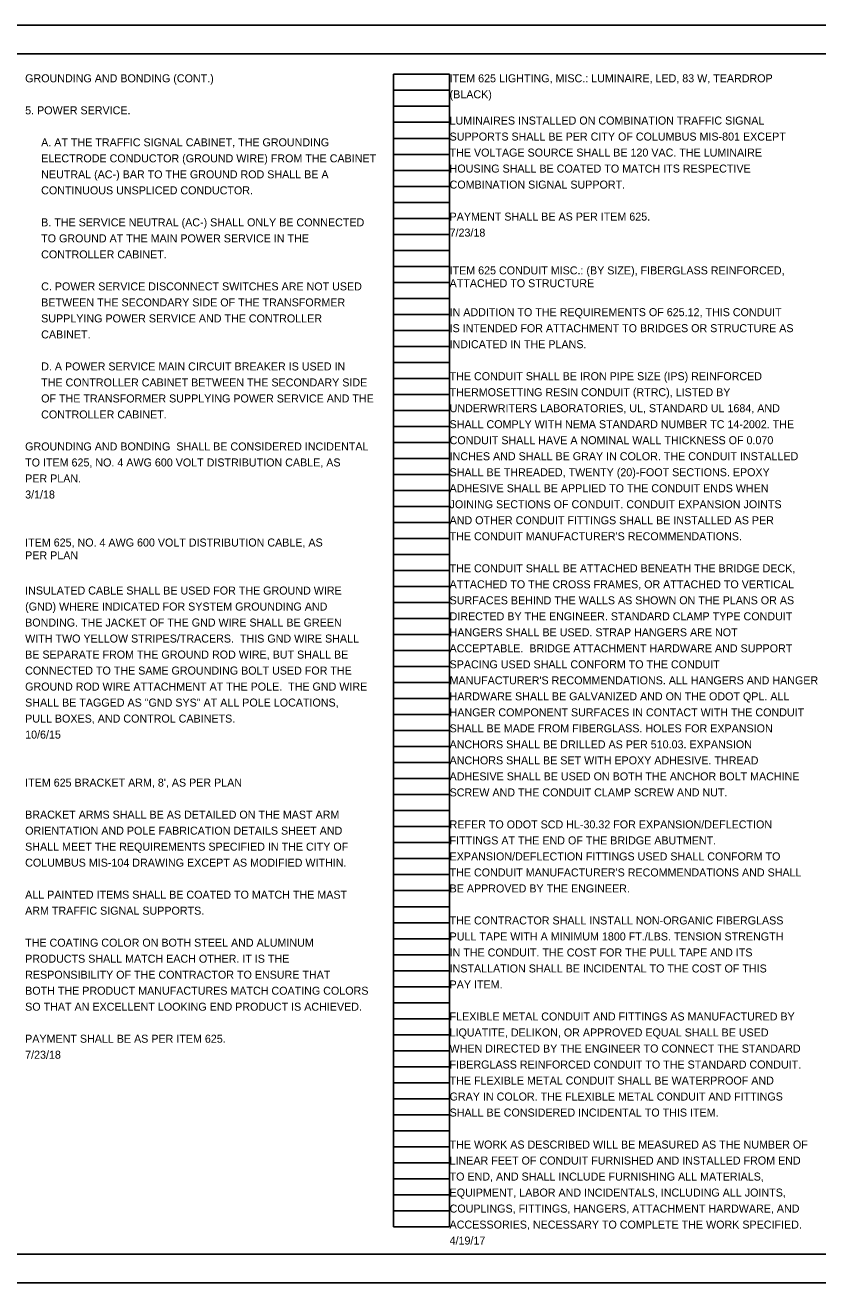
# Model space of a CAD drawing. Extents: x -25.6 to 66.7, y -23.1 to 37.2.
# Drawn here: x 9.81 to 23.67, y -7.51 to 14.49 of the extents above; entities that cross this region are included whole.
import ezdxf

# ---------------------------------------------------------------- set-up
doc = ezdxf.new("R2010")
doc.units = 0
for name, color, linetype in [('PF_P_Text', 7, 'Continuous'), ('SC_Scratch1', 7, 'Continuous'), ('SH_Cut_Line', 7, 'Continuous'), ('SH_Text', 7, 'Continuous')]:
    doc.layers.add(name, color=color, linetype=linetype)

msp = doc.modelspace()

# ---------------------------------------------------------------- linework, layer by layer
at = {"layer": 'PF_P_Text'}
msp.add_lwpolyline([(1.494, 13.992), (32.994, 13.992), (32.994, -7.008), (1.494, -7.008)], close=True, dxfattribs=at)
at = {"layer": 'SC_Scratch1'}
for p, q in [((16.254, -6.528), (16.254, 13.632)), ((16.254, 13.632), (17.234, 13.632)), ((17.234, -6.528), (17.234, 13.632)), ((16.254, 13.352), (17.234, 13.352)), ((16.254, 13.072), (17.234, 13.072)), ((16.254, 12.792), (17.234, 12.792)), ((16.254, 12.512), (17.234, 12.512)), ((16.254, 12.232), (17.234, 12.232)), ((16.254, 11.952), (17.234, 11.952)), ((16.254, 11.672), (17.234, 11.672)), ((16.254, 11.392), (17.234, 11.392)), ((16.254, 11.112), (17.234, 11.112)), ((16.254, 10.832), (17.234, 10.832)), ((16.254, 10.552), (17.234, 10.552)), ((16.254, 10.272), (17.234, 10.272)), ((16.254, 9.992), (17.234, 9.992)), ((16.254, 9.712), (17.234, 9.712)), ((16.254, 9.432), (17.234, 9.432)), ((16.254, 9.152), (17.234, 9.152)), ((16.254, 8.872), (17.234, 8.872)), ((16.254, 8.592), (17.234, 8.592)), ((16.254, 8.312), (17.234, 8.312)), ((16.254, 8.032), (17.234, 8.032)), ((16.254, 7.752), (17.234, 7.752)), ((16.254, 7.472), (17.234, 7.472)), ((16.254, 7.192), (17.234, 7.192)), ((16.254, 6.912), (17.234, 6.912)), ((16.254, 6.632), (17.234, 6.632)), ((16.254, 6.352), (17.234, 6.352)), ((16.254, 6.072), (17.234, 6.072)), ((16.254, 5.792), (17.234, 5.792)), ((16.254, 5.512), (17.234, 5.512)), ((16.254, 5.232), (17.234, 5.232)), ((16.254, 4.952), (17.234, 4.952)), ((16.254, 4.672), (17.234, 4.672)), ((16.254, 4.392), (17.234, 4.392)), ((16.254, 4.112), (17.234, 4.112)), ((16.254, 3.832), (17.234, 3.832)), ((16.254, 3.552), (17.234, 3.552)), ((16.254, 3.272), (17.234, 3.272)), ((16.254, 2.992), (17.234, 2.992)), ((16.254, 2.712), (17.234, 2.712)), ((16.254, 2.432), (17.234, 2.432)), ((16.254, 2.152), (17.234, 2.152)), ((16.254, 1.872), (17.234, 1.872)), ((16.254, 1.592), (17.234, 1.592)), ((16.254, 1.312), (17.234, 1.312)), ((16.254, 1.032), (17.234, 1.032)), ((16.254, 0.752), (17.234, 0.752)), ((16.254, 0.472), (17.234, 0.472)), ((16.254, 0.192), (17.234, 0.192)), ((16.254, -0.088), (17.234, -0.088)), ((16.254, -0.368), (17.234, -0.368)), ((16.254, -0.648), (17.234, -0.648)), ((16.254, -0.928), (17.234, -0.928)), ((16.254, -1.208), (17.234, -1.208)), ((16.254, -1.488), (17.234, -1.488)), ((16.254, -1.768), (17.234, -1.768)), ((16.254, -2.048), (17.234, -2.048)), ((16.254, -2.328), (17.234, -2.328)), ((16.254, -2.608), (17.234, -2.608)), ((16.254, -2.888), (17.234, -2.888)), ((16.254, -3.168), (17.234, -3.168)), ((16.254, -3.448), (17.234, -3.448)), ((16.254, -3.728), (17.234, -3.728)), ((16.254, -4.008), (17.234, -4.008)), ((16.254, -4.288), (17.234, -4.288)), ((16.254, -4.568), (17.234, -4.568)), ((16.254, -4.848), (17.234, -4.848)), ((16.254, -5.128), (17.234, -5.128)), ((16.254, -5.408), (17.234, -5.408)), ((16.254, -5.688), (17.234, -5.688)), ((16.254, -5.968), (17.234, -5.968)), ((16.254, -6.248), (17.234, -6.248)), ((16.254, -6.528), (17.234, -6.528))]:
    msp.add_line(p, q, dxfattribs=at)
at = {"layer": 'SH_Cut_Line'}
msp.add_lwpolyline([(-0.506, -7.508), (33.494, -7.508), (33.494, 14.492), (-0.506, 14.492)], close=True, dxfattribs=at)

# ---------------------------------------------------------------- texts
at = {"layer": 'SH_Text'}
for s, p in [('GROUNDING AND BONDING (CONT.)', (9.814, 13.492)), ('ITEM 625 LIGHTING, MISC.: LUMINAIRE, LED, 83 W, TEARDROP ', (17.234, 13.492)), ('(BLACK)', (17.234, 13.212)), ('5. POWER SERVICE.', (9.814, 12.932)), ('LUMINAIRES INSTALLED ON COMBINATION TRAFFIC SIGNAL ', (17.234, 12.753)), ('SUPPORTS SHALL BE PER CITY OF COLUMBUS MIS-801 EXCEPT ', (17.234, 12.473)), ('A. AT THE TRAFFIC SIGNAL CABINET, THE GROUNDING ', (10.094, 12.372)), ('THE VOLTAGE SOURCE SHALL BE 120 VAC. THE LUMINAIRE ', (17.234, 12.193)), ('ELECTRODE CONDUCTOR (GROUND WIRE) FROM THE CABINET ', (10.094, 12.092)), ('NEUTRAL (AC-) BAR TO THE GROUND ROD SHALL BE A ', (10.094, 11.812)), ('HOUSING SHALL BE COATED TO MATCH ITS RESPECTIVE ', (17.234, 11.913)), ('CONTINUOUS UNSPLICED CONDUCTOR. ', (10.094, 11.532)), ('COMBINATION SIGNAL SUPPORT.', (17.234, 11.633)), ('B. THE SERVICE NEUTRAL (AC-) SHALL ONLY BE CONNECTED ', (10.094, 10.972)), ('PAYMENT SHALL BE AS PER ITEM 625.', (17.234, 11.073)), ('TO GROUND AT THE MAIN POWER SERVICE IN THE ', (10.094, 10.692)), ('7/23/18', (17.234, 10.793)), ('CONTROLLER CABINET.', (10.094, 10.412)), ('ITEM 625 CONDUIT MISC.: (BY SIZE), FIBERGLASS REINFORCED, ', (17.234, 10.132)), ('C. POWER SERVICE DISCONNECT SWITCHES ARE NOT USED ', (10.094, 9.852)), ('ATTACHED TO STRUCTURE', (17.234, 9.907)), ('BETWEEN THE SECONDARY SIDE OF THE TRANSFORMER ', (10.094, 9.572)), ('IN ADDITION TO THE REQUIREMENTS OF 625.12, THIS CONDUIT ', (17.234, 9.401)), ('SUPPLYING POWER SERVICE AND THE CONTROLLER ', (10.094, 9.292)), ('IS INTENDED FOR ATTACHMENT TO BRIDGES OR STRUCTURE AS ', (17.234, 9.121)), ('CABINET.', (10.094, 9.012)), ('INDICATED IN THE PLANS.', (17.234, 8.841)), ('D. A POWER SERVICE MAIN CIRCUIT BREAKER IS USED IN ', (10.094, 8.452)), ('THE CONDUIT SHALL BE IRON PIPE SIZE (IPS) REINFORCED ', (17.234, 8.281)), ('THE CONTROLLER CABINET BETWEEN THE SECONDARY SIDE ', (10.094, 8.172)), ('THERMOSETTING RESIN CONDUIT (RTRC), LISTED BY ', (17.234, 8.001)), ('OF THE TRANSFORMER SUPPLYING POWER SERVICE AND THE ', (10.094, 7.892)), ('CONTROLLER CABINET.', (10.094, 7.612)), ('UNDERWRITERS LABORATORIES, UL, STANDARD UL 1684, AND ', (17.234, 7.721)), ('SHALL COMPLY WITH NEMA STANDARD NUMBER TC 14-2002. THE ', (17.234, 7.441)), ('CONDUIT SHALL HAVE A NOMINAL WALL THICKNESS OF 0.070 ', (17.234, 7.161)), ('GROUNDING AND BONDING  SHALL BE CONSIDERED INCIDENTAL ', (9.814, 7.052)), ('TO ITEM 625, NO. 4 AWG 600 VOLT DISTRIBUTION CABLE, AS ', (9.814, 6.772)), ('INCHES AND SHALL BE GRAY IN COLOR. THE CONDUIT INSTALLED ', (17.234, 6.881)), ('PER PLAN.', (9.814, 6.492)), ('SHALL BE THREADED, TWENTY (20)-FOOT SECTIONS. EPOXY ', (17.234, 6.601)), ('ADHESIVE SHALL BE APPLIED TO THE CONDUIT ENDS WHEN ', (17.234, 6.321)), ('3/1/18', (9.814, 6.212)), ('JOINING SECTIONS OF CONDUIT. CONDUIT EXPANSION JOINTS ', (17.234, 6.041)), ('AND OTHER CONDUIT FITTINGS SHALL BE INSTALLED AS PER ', (17.234, 5.761)), ('ITEM 625, NO. 4 AWG 600 VOLT DISTRIBUTION CABLE, AS ', (9.814, 5.372)), ("THE CONDUIT MANUFACTURER'S RECOMMENDATIONS.", (17.234, 5.481)), ('PER PLAN', (9.814, 5.147)), ('THE CONDUIT SHALL BE ATTACHED BENEATH THE BRIDGE DECK, ', (17.234, 4.921)), ('INSULATED CABLE SHALL BE USED FOR THE GROUND WIRE ', (9.814, 4.532)), ('ATTACHED TO THE CROSS FRAMES, OR ATTACHED TO VERTICAL ', (17.234, 4.641)), ('SURFACES BEHIND THE WALLS AS SHOWN ON THE PLANS OR AS ', (17.234, 4.361)), ('(GND) WHERE INDICATED FOR SYSTEM GROUNDING AND ', (9.814, 4.252)), ('DIRECTED BY THE ENGINEER. STANDARD CLAMP TYPE CONDUIT ', (17.234, 4.081)), ('BONDING. THE JACKET OF THE GND WIRE SHALL BE GREEN ', (9.814, 3.972)), ('WITH TWO YELLOW STRIPES/TRACERS.  THIS GND WIRE SHALL ', (9.814, 3.692)), ('HANGERS SHALL BE USED. STRAP HANGERS ARE NOT ', (17.234, 3.801)), ('BE SEPARATE FROM THE GROUND ROD WIRE, BUT SHALL BE ', (9.814, 3.412)), ('ACCEPTABLE.  BRIDGE ATTACHMENT HARDWARE AND SUPPORT ', (17.234, 3.521)), ('SPACING USED SHALL CONFORM TO THE CONDUIT ', (17.234, 3.241)), ('CONNECTED TO THE SAME GROUNDING BOLT USED FOR THE ', (9.814, 3.132)), ("MANUFACTURER'S RECOMMENDATIONS. ALL HANGERS AND HANGER ", (17.234, 2.961)), ('GROUND ROD WIRE ATTACHMENT AT THE POLE.  THE GND WIRE ', (9.814, 2.852)), ('SHALL BE TAGGED AS "GND SYS" AT ALL POLE LOCATIONS, ', (9.814, 2.572)), ('HARDWARE SHALL BE GALVANIZED AND ON THE ODOT QPL. ALL ', (17.234, 2.681)), ('PULL BOXES, AND CONTROL CABINETS. ', (9.814, 2.292)), ('HANGER COMPONENT SURFACES IN CONTACT WITH THE CONDUIT ', (17.234, 2.401)), ('SHALL BE MADE FROM FIBERGLASS. HOLES FOR EXPANSION ', (17.234, 2.121)), ('10/6/15', (9.814, 2.012)), ('ANCHORS SHALL BE DRILLED AS PER 510.03. EXPANSION ', (17.234, 1.841)), ('ANCHORS SHALL BE SET WITH EPOXY ADHESIVE. THREAD ', (17.234, 1.561)), ('ADHESIVE SHALL BE USED ON BOTH THE ANCHOR BOLT MACHINE ', (17.234, 1.281)), ("ITEM 625 BRACKET ARM, 8', AS PER PLAN", (9.814, 1.172)), ('SCREW AND THE CONDUIT CLAMP SCREW AND NUT.', (17.234, 1.001)), ('BRACKET ARMS SHALL BE AS DETAILED ON THE MAST ARM ', (9.814, 0.612)), ('ORIENTATION AND POLE FABRICATION DETAILS SHEET AND ', (9.814, 0.332)), ('REFER TO ODOT SCD HL-30.32 FOR EXPANSION/DEFLECTION ', (17.234, 0.441)), ('FITTINGS AT THE END OF THE BRIDGE ABUTMENT. ', (17.234, 0.161)), ('SHALL MEET THE REQUIREMENTS SPECIFIED IN THE CITY OF ', (9.814, 0.052)), ('EXPANSION/DEFLECTION FITTINGS USED SHALL CONFORM TO ', (17.234, -0.119)), ('COLUMBUS MIS-104 DRAWING EXCEPT AS MODIFIED WITHIN.', (9.814, -0.228)), ("THE CONDUIT MANUFACTURER'S RECOMMENDATIONS AND SHALL ", (17.234, -0.399)), ('ALL PAINTED ITEMS SHALL BE COATED TO MATCH THE MAST ', (9.814, -0.788)), ('BE APPROVED BY THE ENGINEER.', (17.234, -0.679)), ('ARM TRAFFIC SIGNAL SUPPORTS. ', (9.814, -1.068)), ('THE CONTRACTOR SHALL INSTALL NON-ORGANIC FIBERGLASS ', (17.234, -1.239)), ('THE COATING COLOR ON BOTH STEEL AND ALUMINUM ', (9.814, -1.628)), ('PULL TAPE WITH A MINIMUM 1800 FT./LBS. TENSION STRENGTH ', (17.234, -1.519)), ('IN THE CONDUIT. THE COST FOR THE PULL TAPE AND ITS ', (17.234, -1.799)), ('PRODUCTS SHALL MATCH EACH OTHER. IT IS THE ', (9.814, -1.908)), ('INSTALLATION SHALL BE INCIDENTAL TO THE COST OF THIS ', (17.234, -2.079)), ('RESPONSIBILITY OF THE CONTRACTOR TO ENSURE THAT ', (9.814, -2.188)), ('BOTH THE PRODUCT MANUFACTURES MATCH COATING COLORS ', (9.814, -2.468)), ('PAY ITEM. ', (17.234, -2.359)), ('SO THAT AN EXCELLENT LOOKING END PRODUCT IS ACHIEVED. ', (9.814, -2.748)), ('FLEXIBLE METAL CONDUIT AND FITTINGS AS MANUFACTURED BY ', (17.234, -2.919)), ('LIQUATITE, DELIKON, OR APPROVED EQUAL SHALL BE USED ', (17.234, -3.199)), ('PAYMENT SHALL BE AS PER ITEM 625.', (9.814, -3.308)), ('7/23/18 ', (9.814, -3.588)), ('WHEN DIRECTED BY THE ENGINEER TO CONNECT THE STANDARD ', (17.234, -3.479)), ('FIBERGLASS REINFORCED CONDUIT TO THE STANDARD CONDUIT. ', (17.234, -3.759)), ('THE FLEXIBLE METAL CONDUIT SHALL BE WATERPROOF AND ', (17.234, -4.039)), ('GRAY IN COLOR. THE FLEXIBLE METAL CONDUIT AND FITTINGS ', (17.234, -4.319)), ('SHALL BE CONSIDERED INCIDENTAL TO THIS ITEM.', (17.234, -4.599)), ('THE WORK AS DESCRIBED WILL BE MEASURED AS THE NUMBER OF ', (17.234, -5.159)), ('LINEAR FEET OF CONDUIT FURNISHED AND INSTALLED FROM END ', (17.234, -5.439)), ('TO END, AND SHALL INCLUDE FURNISHING ALL MATERIALS, ', (17.234, -5.719)), ('EQUIPMENT, LABOR AND INCIDENTALS, INCLUDING ALL JOINTS, ', (17.234, -5.999)), ('COUPLINGS, FITTINGS, HANGERS, ATTACHMENT HARDWARE, AND ', (17.234, -6.279)), ('ACCESSORIES, NECESSARY TO COMPLETE THE WORK SPECIFIED.', (17.234, -6.559)), ('4/19/17', (17.234, -6.839))]:
    msp.add_text(s, height=0.14, dxfattribs=at).set_placement(p)

doc.saveas('drawing.dxf')
